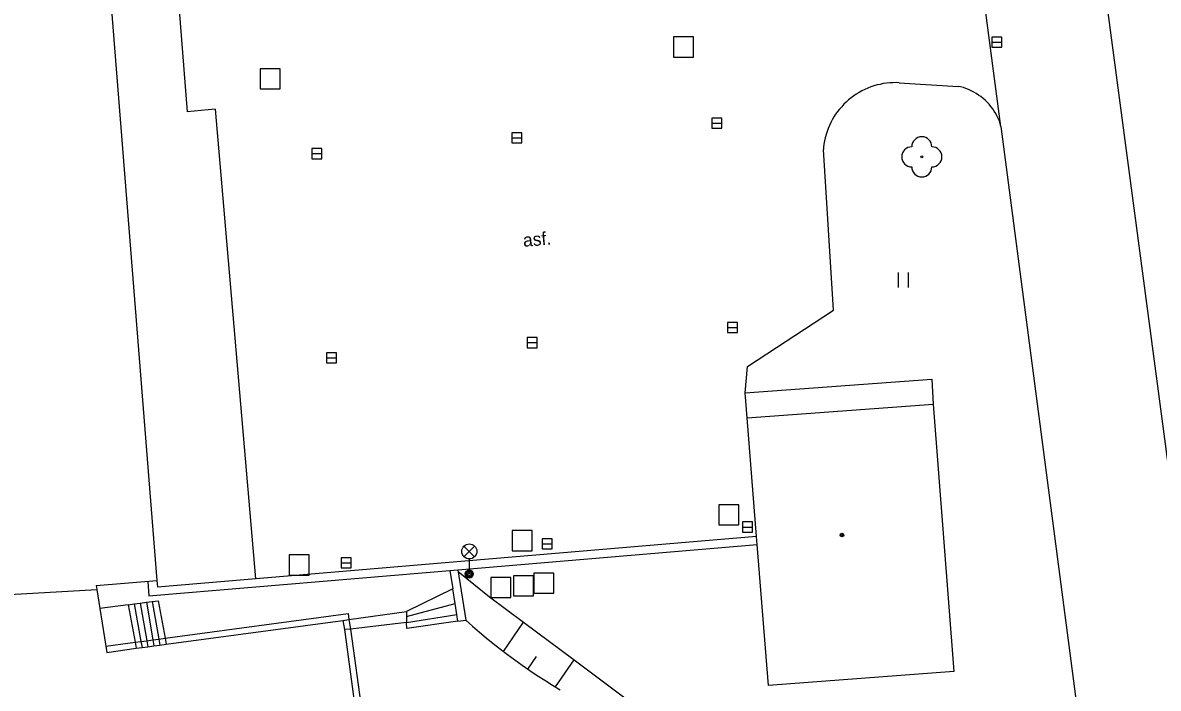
# Model space of a CAD drawing. Extents: x -641829 to -641525, y -1114855 to -1114359.
# Drawn here: x -641768.9 to -641712.4, y -1114569 to -1114535.8 of the extents above; entities that cross this region are included whole.
import ezdxf

# ---------------------------------------------------------------- set-up
doc = ezdxf.new("R2010")
doc.units = 0
for name, color, linetype in [('Vrstva 10', 7, 'Continuous'), ('Vrstva 11', 7, 'Continuous'), ('Vrstva 14', 7, 'Continuous'), ('Vrstva 15', 7, 'Continuous'), ('Vrstva 22', 7, 'Continuous'), ('Vrstva 26', 7, 'Continuous'), ('Vrstva 27', 7, 'Continuous'), ('Vrstva 33', 7, 'Continuous'), ('Vrstva 36', 7, 'Continuous'), ('Vrstva 39', 7, 'Continuous'), ('Vrstva 40', 7, 'Continuous'), ('Vrstva 5', 7, 'Continuous'), ('Vrstva 7', 7, 'Continuous')]:
    doc.layers.add(name, color=color, linetype=linetype)

msp = doc.modelspace()

# ---------------------------------------------------------------- linework, layer by layer
at = {"layer": 'Vrstva 10'}
for p, q in [((-641761.98, -1114524.49), (-641760.74, -1114540.27)), ((-641720.22, -1114541.01), (-641721.74, -1114529.44)), ((-641710.95, -1114564.98), (-641715.11, -1114533.57)), ((-641727, -1114539.16), (-641727.14, -1114539.23)), ((-641726.85, -1114539.1), (-641727, -1114539.16)), ((-641726.7, -1114539.04), (-641726.85, -1114539.1)), ((-641726.55, -1114538.99), (-641726.7, -1114539.04)), ((-641726.39, -1114538.94), (-641726.55, -1114538.99)), ((-641726.24, -1114538.91), (-641726.39, -1114538.94)), ((-641726.08, -1114538.87), (-641726.24, -1114538.91)), ((-641725.92, -1114538.85), (-641726.08, -1114538.87)), ((-641725.76, -1114538.84), (-641725.92, -1114538.85)), ((-641725.6, -1114538.83), (-641725.76, -1114538.84)), ((-641725.44, -1114538.82), (-641725.6, -1114538.83)), ((-641725.28, -1114538.83), (-641725.44, -1114538.82)), ((-641725.28, -1114538.83), (-641722.35, -1114539.01)), ((-641722.23, -1114539.04), (-641722.35, -1114539.01)), ((-641722.09, -1114539.07), (-641722.23, -1114539.04)), ((-641721.96, -1114539.12), (-641722.09, -1114539.07)), ((-641721.83, -1114539.17), (-641721.96, -1114539.12)), ((-641721.7, -1114539.23), (-641721.83, -1114539.17)), ((-641727.81, -1114539.68), (-641727.93, -1114539.79)), ((-641727.68, -1114539.58), (-641727.81, -1114539.68)), ((-641727.55, -1114539.48), (-641727.68, -1114539.58)), ((-641727.42, -1114539.39), (-641727.55, -1114539.48)), ((-641727.28, -1114539.31), (-641727.42, -1114539.39)), ((-641727.14, -1114539.23), (-641727.28, -1114539.31)), ((-641721.57, -1114539.29), (-641721.7, -1114539.23)), ((-641721.45, -1114539.36), (-641721.57, -1114539.29)), ((-641721.33, -1114539.44), (-641721.45, -1114539.36)), ((-641721.22, -1114539.52), (-641721.33, -1114539.44)), ((-641721.11, -1114539.61), (-641721.22, -1114539.52)), ((-641721, -1114539.7), (-641721.11, -1114539.61)), ((-641720.9, -1114539.8), (-641721, -1114539.7)), ((-641759.35, -1114540.14), (-641760.74, -1114540.27)), ((-641759.35, -1114540.14), (-641757.34, -1114563.53)), ((-641728.36, -1114540.26), (-641728.45, -1114540.4)), ((-641728.26, -1114540.14), (-641728.36, -1114540.26)), ((-641728.15, -1114540.02), (-641728.26, -1114540.14)), ((-641728.04, -1114539.9), (-641728.15, -1114540.02)), ((-641727.93, -1114539.79), (-641728.04, -1114539.9)), ((-641720.81, -1114539.9), (-641720.9, -1114539.8)), ((-641720.72, -1114540.01), (-641720.81, -1114539.9)), ((-641720.63, -1114540.12), (-641720.72, -1114540.01)), ((-641720.56, -1114540.24), (-641720.63, -1114540.12)), ((-641720.48, -1114540.36), (-641720.56, -1114540.24)), ((-641728.69, -1114540.81), (-641728.76, -1114540.96)), ((-641728.62, -1114540.67), (-641728.69, -1114540.81)), ((-641728.54, -1114540.53), (-641728.62, -1114540.67)), ((-641728.45, -1114540.4), (-641728.54, -1114540.53)), ((-641720.42, -1114540.48), (-641720.48, -1114540.36)), ((-641720.36, -1114540.61), (-641720.42, -1114540.48)), ((-641720.3, -1114540.74), (-641720.36, -1114540.61)), ((-641720.26, -1114540.88), (-641720.3, -1114540.74)), ((-641728.93, -1114541.41), (-641728.97, -1114541.57)), ((-641728.88, -1114541.26), (-641728.93, -1114541.41)), ((-641728.83, -1114541.11), (-641728.88, -1114541.26)), ((-641728.76, -1114540.96), (-641728.83, -1114541.11)), ((-641720.22, -1114541.01), (-641720.26, -1114540.88)), ((-641720.22, -1114541.01), (-641716.43, -1114570.02)), ((-641729.03, -1114541.88), (-641729.06, -1114542.04)), ((-641729.01, -1114541.72), (-641729.03, -1114541.88)), ((-641728.97, -1114541.57), (-641729.01, -1114541.72)), ((-641729.06, -1114542.04), (-641729.06, -1114542.15)), ((-641728.56, -1114550.15), (-641729.06, -1114542.15)), ((-641732.84, -1114552.95), (-641728.56, -1114550.15)), ((-641732.96, -1114554.27), (-641732.84, -1114552.95)), ((-641746.87, -1114565.58), (-641746.53, -1114565.88)), ((-641746.53, -1114565.88), (-641746.19, -1114566.18)), ((-641746.19, -1114566.18), (-641745.85, -1114566.47)), ((-641745.85, -1114566.47), (-641745.5, -1114566.75)), ((-641745.5, -1114566.75), (-641745.14, -1114567.03)), ((-641745.14, -1114567.03), (-641744.78, -1114567.3)), ((-641744.78, -1114567.3), (-641744.42, -1114567.57)), ((-641744.42, -1114567.57), (-641744.05, -1114567.83)), ((-641744.05, -1114567.83), (-641743.68, -1114568.09)), ((-641743.68, -1114568.09), (-641743.31, -1114568.34)), ((-641743.31, -1114568.34), (-641742.93, -1114568.58)), ((-641742.93, -1114568.58), (-641742.54, -1114568.82)), ((-641742.54, -1114568.82), (-641742.16, -1114569.05))]:
    msp.add_line(p, q, dxfattribs=at)
at = {"layer": 'Vrstva 11'}
for p, q in [((-641747.66, -1114563.11), (-641747.51, -1114564.03)), ((-641747.26, -1114563.08), (-641746.87, -1114565.58)), ((-641747.51, -1114564.03), (-641749.81, -1114565.16)), ((-641747.4, -1114564.75), (-641747.51, -1114564.03)), ((-641763.67, -1114564.82), (-641765.08, -1114565)), ((-641763.67, -1114564.82), (-641763.37, -1114564.78)), ((-641763.67, -1114564.82), (-641763.33, -1114566.69)), ((-641763.37, -1114564.78), (-641763.07, -1114564.74)), ((-641763.37, -1114564.78), (-641763.04, -1114566.65)), ((-641763.07, -1114564.74), (-641762.77, -1114564.7)), ((-641763.07, -1114564.74), (-641762.74, -1114566.61)), ((-641762.77, -1114564.7), (-641762.48, -1114564.66)), ((-641762.77, -1114564.7), (-641762.44, -1114566.57)), ((-641762.48, -1114564.66), (-641762.18, -1114564.62)), ((-641762.48, -1114564.66), (-641762.14, -1114566.53)), ((-641762.18, -1114564.62), (-641761.84, -1114566.49)), ((-641749.81, -1114565.41), (-641747.4, -1114564.75)), ((-641747.31, -1114565.3), (-641747.4, -1114564.75)), ((-641749.81, -1114565.7), (-641747.31, -1114565.3)), ((-641749.8, -1114566.01), (-641749.81, -1114565.7)), ((-641747.26, -1114565.64), (-641749.8, -1114566.01)), ((-641747.26, -1114565.64), (-641747.31, -1114565.3)), ((-641747.26, -1114565.64), (-641746.87, -1114565.58)), ((-641763.33, -1114566.69), (-641763.28, -1114566.99)), ((-641763.04, -1114566.65), (-641762.98, -1114566.95)), ((-641762.74, -1114566.61), (-641762.69, -1114566.91)), ((-641762.44, -1114566.57), (-641762.39, -1114566.87)), ((-641762.14, -1114566.53), (-641762.09, -1114566.83)), ((-641761.84, -1114566.49), (-641761.79, -1114566.79))]:
    msp.add_line(p, q, dxfattribs=at)
at = {"layer": 'Vrstva 14'}
for p, q in [((-641747.24, -1114563.16), (-641745.68, -1114564.43)), ((-641745.68, -1114564.43), (-641743.99, -1114565.69)), ((-641743.99, -1114565.69), (-641741.47, -1114567.57)), ((-641741.47, -1114567.57), (-641735.8, -1114571.8))]:
    msp.add_line(p, q, dxfattribs=at)
at = {"layer": 'Vrstva 15'}
for p, q in [((-641744.98, -1114567.15), (-641743.99, -1114565.69)), ((-641743.77, -1114568.02), (-641743.35, -1114567.4)), ((-641742.39, -1114568.91), (-641741.47, -1114567.57))]:
    msp.add_line(p, q, dxfattribs=at)
at = {"layer": 'Vrstva 22'}
msp.add_circle((-641724.16, -1114542.52), 0.05, dxfattribs=at)
for centre, start, end in [((-641724.16, -1114542.02), 0, 180), ((-641724.66, -1114542.52), 90, 270), ((-641723.66, -1114542.52), 270, 90), ((-641724.16, -1114543.02), 180, 0)]:
    msp.add_arc(centre, 0.5, start, end, dxfattribs=at)
at = {"layer": 'Vrstva 26'}
for points in [[(-641736.53, -1114537.55), (-641735.53, -1114537.55), (-641735.53, -1114536.55), (-641736.53, -1114536.55)], [(-641757.1, -1114539.13), (-641756.1, -1114539.13), (-641756.1, -1114538.13), (-641757.1, -1114538.13)], [(-641734.27, -1114560.84), (-641733.27, -1114560.84), (-641733.27, -1114559.84), (-641734.27, -1114559.84)], [(-641744.56, -1114562.13), (-641743.56, -1114562.13), (-641743.56, -1114561.13), (-641744.56, -1114561.13)], [(-641755.66, -1114563.34), (-641754.66, -1114563.34), (-641754.66, -1114562.34), (-641755.66, -1114562.34)], [(-641745.62, -1114564.46), (-641744.62, -1114564.46), (-641744.62, -1114563.46), (-641745.62, -1114563.46)], [(-641744.49, -1114564.38), (-641743.49, -1114564.38), (-641743.49, -1114563.38), (-641744.49, -1114563.38)], [(-641743.48, -1114564.24), (-641742.48, -1114564.24), (-641742.48, -1114563.24), (-641743.48, -1114563.24)]]:
    msp.add_lwpolyline(points, close=True, dxfattribs=at)
at = {"layer": 'Vrstva 27'}
for p, q in [((-641720.68, -1114536.81), (-641720.18, -1114536.81)), ((-641734.62, -1114540.84), (-641734.12, -1114540.84)), ((-641744.58, -1114541.57), (-641744.08, -1114541.57)), ((-641754.53, -1114542.36), (-641754.03, -1114542.36)), ((-641733.84, -1114551.01), (-641733.34, -1114551.01)), ((-641743.81, -1114551.77), (-641743.31, -1114551.77)), ((-641753.8, -1114552.53), (-641753.3, -1114552.53)), ((-641733.09, -1114560.95), (-641732.59, -1114560.95)), ((-641743.06, -1114561.79), (-641742.56, -1114561.79)), ((-641753.07, -1114562.74), (-641752.57, -1114562.74))]:
    msp.add_line(p, q, dxfattribs=at)
for points in [[(-641720.68, -1114537.06), (-641720.18, -1114537.06), (-641720.18, -1114536.56), (-641720.68, -1114536.56)], [(-641734.62, -1114541.09), (-641734.12, -1114541.09), (-641734.12, -1114540.59), (-641734.62, -1114540.59)], [(-641744.58, -1114541.82), (-641744.08, -1114541.82), (-641744.08, -1114541.32), (-641744.58, -1114541.32)], [(-641754.53, -1114542.61), (-641754.03, -1114542.61), (-641754.03, -1114542.11), (-641754.53, -1114542.11)], [(-641733.84, -1114551.26), (-641733.34, -1114551.26), (-641733.34, -1114550.76), (-641733.84, -1114550.76)], [(-641743.81, -1114552.02), (-641743.31, -1114552.02), (-641743.31, -1114551.52), (-641743.81, -1114551.52)], [(-641753.8, -1114552.78), (-641753.3, -1114552.78), (-641753.3, -1114552.28), (-641753.8, -1114552.28)], [(-641733.09, -1114561.2), (-641732.59, -1114561.2), (-641732.59, -1114560.7), (-641733.09, -1114560.7)], [(-641743.06, -1114562.04), (-641742.56, -1114562.04), (-641742.56, -1114561.54), (-641743.06, -1114561.54)], [(-641753.07, -1114562.99), (-641752.57, -1114562.99), (-641752.57, -1114562.49), (-641753.07, -1114562.49)]]:
    msp.add_lwpolyline(points, close=True, dxfattribs=at)
at = {"layer": 'Vrstva 33'}
for p, q in [((-641746.956, -1114562.43), (-641746.424, -1114561.9)), ((-641746.956, -1114561.9), (-641746.424, -1114562.43)), ((-641746.69, -1114562.54), (-641746.69, -1114563.29))]:
    msp.add_line(p, q, dxfattribs=at)
for centre, radius in [((-641746.69, -1114562.165), 0.375), ((-641746.69, -1114563.29), 0.2), ((-641746.69, -1114563.29), 0.145), ((-641746.69, -1114563.29), 0.0876)]:
    msp.add_circle(centre, radius, dxfattribs=at)
at = {"layer": 'Vrstva 36'}
for p, q in [((-641725.324, -1114549.024), (-641725.324, -1114548.272)), ((-641724.824, -1114549.024), (-641724.824, -1114548.272))]:
    msp.add_line(p, q, dxfattribs=at)
at = {"layer": 'Vrstva 39'}
for radius in [0.09, 0.0398]:
    msp.add_circle((-641728.14, -1114561.35), radius, dxfattribs=at)
at = {"layer": 'Vrstva 5'}
for p, q in [((-641765.34, -1114524.75), (-641762.25, -1114563.62)), ((-641732.96, -1114554.27), (-641723.66, -1114553.59)), ((-641723.66, -1114553.59), (-641723.59, -1114554.83)), ((-641732.86, -1114555.51), (-641732.96, -1114554.27)), ((-641732.86, -1114555.51), (-641723.59, -1114554.83)), ((-641723.59, -1114554.83), (-641722.57, -1114568.14)), ((-641732.39, -1114561.42), (-641732.86, -1114555.51)), ((-641732.36, -1114561.82), (-641732.39, -1114561.42)), ((-641731.79, -1114568.84), (-641732.36, -1114561.82)), ((-641765.26, -1114563.86), (-641762.25, -1114563.62)), ((-641765.26, -1114563.86), (-641765.23, -1114564.06)), ((-641776.44, -1114564.71), (-641765.23, -1114564.06)), ((-641765.23, -1114564.06), (-641765.08, -1114565)), ((-641765.08, -1114565), (-641764.73, -1114567.19)), ((-641752.68, -1114565.56), (-641749.81, -1114565.16)), ((-641749.81, -1114565.16), (-641749.81, -1114565.7)), ((-641761.84, -1114566.49), (-641752.72, -1114565.26)), ((-641761.79, -1114566.79), (-641752.98, -1114565.6)), ((-641752.98, -1114565.6), (-641752.68, -1114565.56)), ((-641752.98, -1114565.6), (-641752.91, -1114566.06)), ((-641752.72, -1114565.26), (-641752.68, -1114565.56)), ((-641752.68, -1114565.56), (-641752.61, -1114566.03)), ((-641749.81, -1114565.7), (-641752.61, -1114566.03)), ((-641752.61, -1114566.03), (-641752.91, -1114566.06)), ((-641752.91, -1114566.06), (-641751.01, -1114579.9)), ((-641752.61, -1114566.03), (-641751.2, -1114576.3)), ((-641764.78, -1114566.89), (-641763.33, -1114566.69)), ((-641763.33, -1114566.69), (-641763.04, -1114566.65)), ((-641763.04, -1114566.65), (-641762.74, -1114566.61)), ((-641762.74, -1114566.61), (-641762.44, -1114566.57)), ((-641762.69, -1114566.91), (-641762.39, -1114566.87)), ((-641762.44, -1114566.57), (-641762.14, -1114566.53)), ((-641762.39, -1114566.87), (-641762.09, -1114566.83)), ((-641762.14, -1114566.53), (-641761.84, -1114566.49)), ((-641762.09, -1114566.83), (-641761.79, -1114566.79)), ((-641764.73, -1114567.19), (-641763.28, -1114566.99)), ((-641763.28, -1114566.99), (-641762.98, -1114566.95)), ((-641762.98, -1114566.95), (-641762.69, -1114566.91)), ((-641722.57, -1114568.14), (-641731.79, -1114568.84))]:
    msp.add_line(p, q, dxfattribs=at)
at = {"layer": 'Vrstva 7'}
for p, q in [((-641732.39, -1114561.42), (-641762.22, -1114563.94)), ((-641747.26, -1114563.08), (-641732.36, -1114561.82)), ((-641762.64, -1114564.38), (-641747.26, -1114563.08)), ((-641762.69, -1114563.66), (-641762.64, -1114564.38)), ((-641762.25, -1114563.62), (-641762.22, -1114563.94))]:
    msp.add_line(p, q, dxfattribs=at)

# ---------------------------------------------------------------- texts
at = {"layer": 'Vrstva 40'}
msp.add_text('asf.', height=0.65, rotation=4.8299, dxfattribs=at).set_placement((-641743.99, -1114547))

doc.saveas('drawing.dxf')
